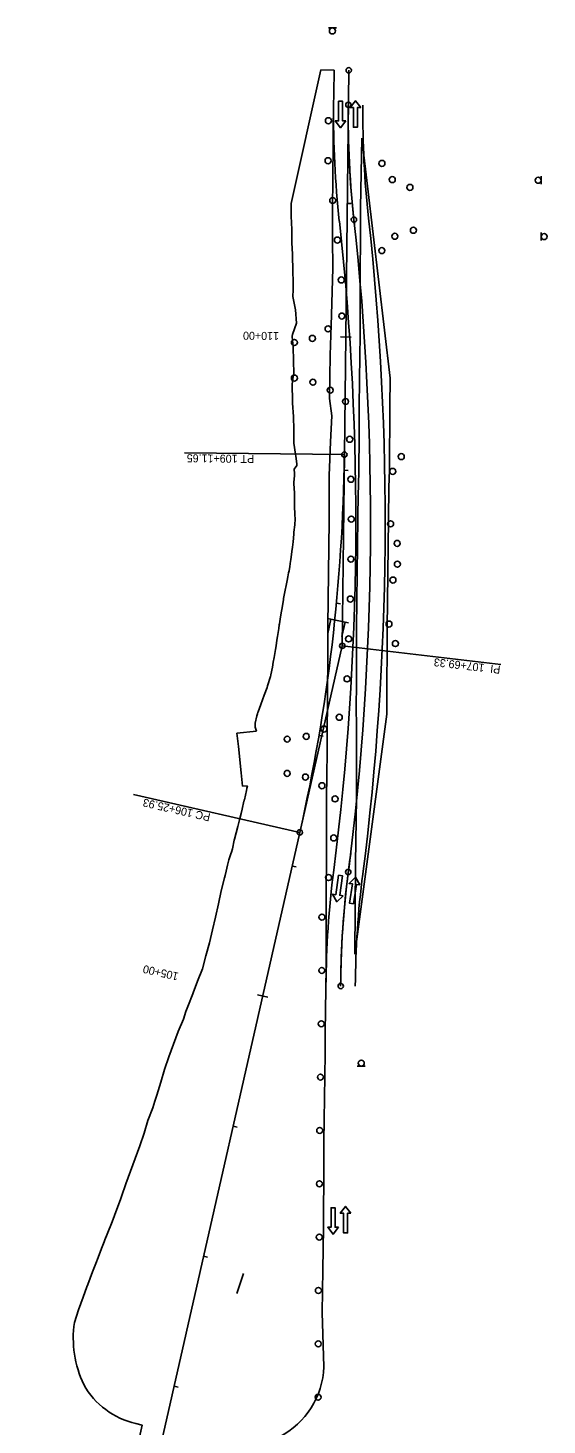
# Model space of a CAD drawing. Extents: x 1710760 to 1712674, y 548603 to 551129.
# Drawn here: x 1712247 to 1712636, y 550081 to 551129 of the extents above; entities that cross this region are included whole.
import ezdxf

# ---------------------------------------------------------------- set-up
doc = ezdxf.new("R2010")
doc.units = 0
for name, color, linetype in [('R_Concrete', 7, 'Continuous'), ('R_Horz Alg', 7, 'Continuous'), ('R_Horz Alg Annot', 7, 'Continuous'), ('R_MOT', 7, 'Continuous'), ('R_Striping', 7, 'Continuous')]:
    doc.layers.add(name, color=color, linetype=linetype)

msp = doc.modelspace()

# ---------------------------------------------------------------- linework, layer by layer
at = {"layer": 'R_Concrete'}
msp.add_line((1712408.5, 550195), (1712403.5, 550179.9), dxfattribs=at)
at = {"layer": 'R_Horz Alg'}
for p, q in [((1712484.2, 550809.1), (1712487.5, 551097.3)), ((1712484.2, 550809.1), (1712487.5, 551097.3)), ((1712246.8, 549627.3), (1712450.8, 550525.8)), ((1712246.8, 549627.3), (1712450.8, 550525.8))]:
    msp.add_line(p, q, dxfattribs=at)
for centre, radius, start, end in [((1713203.3, 551063.2), 716.2, 179.3424, 186.2485), ((1710420.3, 550758.5), 2083.5, 352.7611, 6.2485), ((1711136.1, 550824.3), 1348.1, 347.2066, 359.3498), ((1711136.1, 550824.3), 1348.1, 347.2066, 359.3498), ((1713197.6, 550405.7), 716.2, 172.7611, 179.6146)]:
    msp.add_arc(centre, radius, start, end, dxfattribs=at)
at = {"layer": 'R_Horz Alg Annot'}
for p, q in [((1712482.6, 550665.7), (1712484.2, 550809.1)), ((1712482.6, 550665.7), (1712484.2, 550809.1)), ((1712450.8, 550525.8), (1712482.6, 550665.7)), ((1712450.8, 550525.8), (1712482.6, 550665.7))]:
    msp.add_line(p, q, dxfattribs=at)
for points in [[(1712489.3, 550997.4), (1712486.3, 550997.4)], [(1712481.2, 550897.4), (1712489.2, 550897.3)], [(1712484.2, 550809.1), (1712364.2, 550810.4)], [(1712487, 550797.3), (1712484, 550797.4)], [(1712481.3, 550697.3), (1712478.3, 550697.6)], [(1712482.6, 550665.7), (1712601.7, 550651.6)], [(1712468.2, 550598), (1712465.2, 550598.5)], [(1712450.8, 550525.8), (1712326.1, 550554.2)], [(1712448, 550499.9), (1712445.1, 550500.5)], [(1712419, 550403.9), (1712426.8, 550402.1)], [(1712403.7, 550304.8), (1712400.8, 550305.5)], [(1712381.6, 550207.3), (1712378.6, 550208)], [(1712359.4, 550109.8), (1712356.5, 550110.5)]]:
    msp.add_lwpolyline(points, dxfattribs=at)
for centre in [(1712487.5, 551097.3), (1712487.5, 551097.3), (1712487.2, 551071.4), (1712491.4, 550985.3), (1712484.2, 550809.1), (1712484.2, 550809.1), (1712482.6, 550665.7), (1712482.6, 550665.7), (1712450.8, 550525.8), (1712450.8, 550525.8), (1712487.1, 550496), (1712481.5, 550410.5)]:
    msp.add_circle(centre, 2, dxfattribs=at)
at = {"layer": 'R_MOT'}
for p, q in [((1712472.2, 551129.1), (1712478.2, 551129.1)), ((1712518.6, 550866.5), (1712497.3, 551046.5)), ((1712631.8, 551017.8), (1712631.8, 551011.8)), ((1712631.8, 550969.6), (1712631.8, 550975.6)), ((1712446.3, 550869.8), (1712445.8, 550889.8)), ((1712446.3, 550869.8), (1712445.8, 550889.8)), ((1712487.3, 550682.9), (1712471.6, 550686.2)), ((1712471.8, 550675), (1712474.1, 550685.7)), ((1712482.4, 550672.7), (1712484.7, 550683.4)), ((1712492.1, 550434.5), (1712516.1, 550614.5)), ((1712403.6, 550600.2), (1712418.3, 550601.8)), ((1712403.6, 550600.2), (1712418.3, 550601.8)), ((1712404.7, 550590.3), (1712403.6, 550600.2)), ((1712404.7, 550590.3), (1712403.6, 550600.2)), ((1712406.8, 550570.4), (1712404.7, 550590.3)), ((1712406.8, 550570.4), (1712404.7, 550590.3)), ((1712407.9, 550560.4), (1712406.8, 550570.4)), ((1712407.9, 550560.4), (1712406.8, 550570.4)), ((1712411.5, 550560.8), (1712407.9, 550560.4)), ((1712411.5, 550560.8), (1712407.9, 550560.4)), ((1712499.9, 550350.4), (1712493.9, 550350.4)), ((1712311, 549985), (1712332.5, 550081.3)), ((1712311, 549985), (1712332.5, 550081.3)), ((1712332.5, 550081.3), (1712327.7, 550082.4)), ((1712332.5, 550081.3), (1712327.7, 550082.4))]:
    msp.add_line(p, q, dxfattribs=at)
for points in [[(1712444.2, 550997.5), (1712466.6, 551097.6), (1712476.6, 551097.5)], [(1712444.2, 550997.5), (1712466.6, 551097.6), (1712476.6, 551097.5)], [(1712476.6, 551097.5), (1712476.5, 551095.4), (1712476.3, 551081.9), (1712476.1, 551068.3), (1712475.9, 551054.8), (1712475.7, 551041.2), (1712475.5, 551017), (1712475.4, 550992.8), (1712475.4, 550970.9), (1712475.5, 550949), (1712475.1, 550931.4), (1712474.6, 550913.9), (1712474.1, 550898.7), (1712473.5, 550883.6), (1712473.2, 550867.3), (1712473, 550851.1), (1712474.7, 550838.2), (1712473.9, 550818.8), (1712473.1, 550799.5), (1712472.9, 550793.7), (1712472.8, 550791.4), (1712472.8, 550775.5), (1712472.7, 550759.7), (1712472.5, 550739.9), (1712472.3, 550720.2), (1712472.1, 550700.5), (1712471.9, 550680.8), (1712471.8, 550665.9), (1712471.7, 550651), (1712471.6, 550636.1), (1712471.5, 550621.2), (1712471.4, 550603.7), (1712471.2, 550586.2), (1712471.1, 550568.6), (1712470.9, 550551.1), (1712470.9, 550534.8), (1712470.8, 550518.4), (1712470.7, 550502.1), (1712470.6, 550485.8), (1712470.6, 550470.5), (1712470.6, 550455.2), (1712470.5, 550439.9), (1712470.5, 550424.6), (1712470.3, 550408.4), (1712470.1, 550392.2), (1712469.9, 550376), (1712469.7, 550359.8), (1712469.5, 550343.3), (1712469.2, 550326.8), (1712469, 550310.3), (1712468.7, 550293.8), (1712468.7, 550277.7), (1712468.7, 550261.6), (1712468.6, 550245.4), (1712468.6, 550229.3), (1712468.4, 550213.4), (1712468.1, 550197.6), (1712467.9, 550181.7), (1712467.6, 550165.8), (1712468.8, 550124.9), (1712468.8, 550124.9)], [(1712476.6, 551097.5), (1712476.5, 551095.4), (1712476.3, 551081.9), (1712476.1, 551068.3), (1712475.9, 551054.8), (1712475.7, 551041.2), (1712475.5, 551017), (1712475.4, 550992.8), (1712475.4, 550970.9), (1712475.5, 550949), (1712475.1, 550931.4), (1712474.6, 550913.9), (1712474.1, 550898.7), (1712473.5, 550883.6), (1712473.2, 550867.3), (1712473, 550851.1), (1712474.7, 550838.2), (1712473.9, 550818.8), (1712473.1, 550799.5), (1712472.9, 550793.7), (1712472.8, 550791.4), (1712472.8, 550775.5), (1712472.7, 550759.7), (1712472.5, 550739.9), (1712472.3, 550720.2), (1712472.1, 550700.5), (1712471.9, 550680.8), (1712471.8, 550665.9), (1712471.7, 550651), (1712471.6, 550636.1), (1712471.5, 550621.2), (1712471.4, 550603.7), (1712471.2, 550586.2), (1712471.1, 550568.6), (1712470.9, 550551.1), (1712470.9, 550534.8), (1712470.8, 550518.4), (1712470.7, 550502.1), (1712470.6, 550485.8), (1712470.6, 550470.5), (1712470.6, 550455.2), (1712470.5, 550439.9), (1712470.5, 550424.6), (1712470.3, 550408.4), (1712470.1, 550392.2), (1712469.9, 550376), (1712469.7, 550359.8), (1712469.5, 550343.3), (1712469.2, 550326.8), (1712469, 550310.3), (1712468.7, 550293.8), (1712468.7, 550277.7), (1712468.7, 550261.6), (1712468.6, 550245.4), (1712468.6, 550229.3), (1712468.4, 550213.4), (1712468.1, 550197.6), (1712467.9, 550181.7), (1712467.6, 550165.8), (1712468.8, 550124.9), (1712468.8, 550124.9)], [(1712497.3, 551046.5), (1712496.4, 550994.1), (1712496.3, 550970.5), (1712496.1, 550946.9), (1712496.1, 550929.6), (1712496, 550912.4), (1712496, 550897.9), (1712495.9, 550883.5), (1712495.6, 550864.5), (1712495.3, 550845.5), (1712495.2, 550821.9), (1712495.1, 550798.3), (1712494.7, 550785.1), (1712494.6, 550779.9), (1712494.3, 550761.1), (1712494, 550740.6), (1712493.8, 550720.1), (1712493.6, 550699.6), (1712493.4, 550679), (1712493.3, 550664.5), (1712493.2, 550650), (1712493.2, 550635.6), (1712493.1, 550621.1), (1712493.2, 550603.6), (1712493.2, 550586.2), (1712493.3, 550568.8), (1712493.4, 550551.4), (1712493.1, 550535.2), (1712492.8, 550519), (1712492.6, 550502.7), (1712492.1, 550434.5)], [(1712445.8, 550889.8), (1712445, 550897.8), (1712445, 550897.9), (1712445.2, 550899.2), (1712448.4, 550907.8), (1712447.6, 550917.8), (1712445.6, 550927.8), (1712445.7, 550932.8), (1712445.7, 550937.8), (1712445.6, 550947.8), (1712445.2, 550957.9), (1712445.2, 550959.5), (1712444.9, 550967.9), (1712444.8, 550977.9), (1712444.4, 550987.9), (1712444.2, 550997.5)], [(1712445.8, 550889.8), (1712445, 550897.8), (1712445, 550897.9), (1712445.2, 550899.2), (1712448.4, 550907.8), (1712447.6, 550917.8), (1712445.6, 550927.8), (1712445.7, 550932.8), (1712445.7, 550937.8), (1712445.6, 550947.8), (1712445.2, 550957.9), (1712445.2, 550959.5), (1712444.9, 550967.9), (1712444.8, 550977.9), (1712444.4, 550987.9), (1712444.2, 550997.5)], [(1712444.8, 550736.4), (1712445.2, 550739.8), (1712445.7, 550743.7), (1712446.3, 550749.5), (1712446.4, 550750.9), (1712447, 550756.4), (1712447.1, 550758.2), (1712447.2, 550759.2), (1712447.2, 550760.8), (1712447.1, 550764.2), (1712447, 550765.6), (1712446.9, 550768.9), (1712446.8, 550772.9), (1712446.8, 550778.7), (1712446.7, 550780.2), (1712446.4, 550787.5), (1712446.4, 550788.4), (1712446.7, 550793.1), (1712446.7, 550794.9), (1712446.5, 550798.2), (1712448.6, 550800.9), (1712448.5, 550802.1), (1712447.7, 550807.9), (1712447.5, 550809.5), (1712446.4, 550817.8), (1712446.2, 550826.2), (1712446.2, 550827.8), (1712446, 550837.8), (1712445.3, 550847.8), (1712445.2, 550853.5), (1712445, 550857.8), (1712445, 550861.9), (1712445.9, 550867.8), (1712446.3, 550869.8)], [(1712444.8, 550736.4), (1712445.2, 550739.8), (1712445.7, 550743.7), (1712446.3, 550749.5), (1712446.4, 550750.9), (1712447, 550756.4), (1712447.1, 550758.2), (1712447.2, 550759.2), (1712447.2, 550760.8), (1712447.1, 550764.2), (1712447, 550765.6), (1712446.9, 550768.9), (1712446.8, 550772.9), (1712446.8, 550778.7), (1712446.7, 550780.2), (1712446.4, 550787.5), (1712446.4, 550788.4), (1712446.7, 550793.1), (1712446.7, 550794.9), (1712446.5, 550798.2), (1712448.6, 550800.9), (1712448.5, 550802.1), (1712447.7, 550807.9), (1712447.5, 550809.5), (1712446.4, 550817.8), (1712446.2, 550826.2), (1712446.2, 550827.8), (1712446, 550837.8), (1712445.3, 550847.8), (1712445.2, 550853.5), (1712445, 550857.8), (1712445, 550861.9), (1712445.9, 550867.8), (1712446.3, 550869.8)], [(1712516.1, 550614.5), (1712516.1, 550621), (1712516.4, 550678.9), (1712517.3, 550760.8), (1712517.7, 550784.5), (1712518.1, 550797.8), (1712518.3, 550845.3), (1712518.6, 550866.5)], [(1712418.3, 550601.8), (1712417.4, 550604.8), (1712417.3, 550606.6), (1712417.3, 550607.1), (1712417.3, 550607.6), (1712417.3, 550607.7), (1712418.5, 550613.3), (1712419, 550614.8), (1712419.3, 550616), (1712419.5, 550616.3), (1712421.5, 550621.7), (1712422.8, 550625.3), (1712424.1, 550628.7), (1712426.2, 550634.5), (1712426.6, 550635.6), (1712428.7, 550642.7), (1712429, 550643.8), (1712429, 550643.9), (1712430.2, 550649.8), (1712430.9, 550653.4), (1712431.6, 550657), (1712432.5, 550663), (1712432.7, 550664.2), (1712433.9, 550671.4), (1712434.1, 550672.6), (1712435, 550678.6), (1712435.4, 550681.4), (1712435.6, 550682.1), (1712436.1, 550685.8), (1712436.6, 550689), (1712437, 550691.7), (1712437.2, 550693), (1712438.5, 550700.2), (1712438.6, 550701.3), (1712439.8, 550707.4), (1712440.5, 550710.9), (1712441.2, 550714.7), (1712441.7, 550717.5), (1712442.4, 550720.5), (1712442.7, 550721.9), (1712443.2, 550725.2), (1712443.9, 550729.1), (1712444, 550730.1), (1712444.8, 550736.4)], [(1712418.3, 550601.8), (1712417.4, 550604.8), (1712417.3, 550606.6), (1712417.3, 550607.1), (1712417.3, 550607.6), (1712417.3, 550607.7), (1712418.5, 550613.3), (1712419, 550614.8), (1712419.3, 550616), (1712419.5, 550616.3), (1712421.5, 550621.7), (1712422.8, 550625.3), (1712424.1, 550628.7), (1712426.2, 550634.5), (1712426.6, 550635.6), (1712428.7, 550642.7), (1712429, 550643.8), (1712429, 550643.9), (1712430.2, 550649.8), (1712430.9, 550653.4), (1712431.6, 550657), (1712432.5, 550663), (1712432.7, 550664.2), (1712433.9, 550671.4), (1712434.1, 550672.6), (1712435, 550678.6), (1712435.4, 550681.4), (1712435.6, 550682.1), (1712436.1, 550685.8), (1712436.6, 550689), (1712437, 550691.7), (1712437.2, 550693), (1712438.5, 550700.2), (1712438.6, 550701.3), (1712439.8, 550707.4), (1712440.5, 550710.9), (1712441.2, 550714.7), (1712441.7, 550717.5), (1712442.4, 550720.5), (1712442.7, 550721.9), (1712443.2, 550725.2), (1712443.9, 550729.1), (1712444, 550730.1), (1712444.8, 550736.4)], [(1712281.6, 550158.2), (1712284.7, 550167.8), (1712288.1, 550177.3), (1712291, 550184.9), (1712291.6, 550186.7), (1712295.3, 550196.2), (1712298.2, 550203.8), (1712298.9, 550205.6), (1712302.6, 550215), (1712304, 550218.7), (1712304.6, 550220.3), (1712306.2, 550224.4), (1712309.9, 550233.8), (1712313.5, 550243.3), (1712316.2, 550250.4), (1712317, 550252.8), (1712320.2, 550262.3), (1712323.7, 550271.7), (1712327.3, 550281.2), (1712330.7, 550290.7), (1712333.9, 550300.2), (1712336.8, 550309.8), (1712340.4, 550319.2), (1712341.9, 550324.1), (1712343.4, 550328.8), (1712346.4, 550338.4), (1712349.3, 550348), (1712352.5, 550357.5), (1712356.1, 550366.9), (1712359.6, 550376.4), (1712363.4, 550385.8), (1712365.3, 550391.4), (1712366.8, 550395.3), (1712370.5, 550404.7), (1712370.8, 550405.5), (1712374.1, 550414.1), (1712377.8, 550423.5), (1712380.3, 550433.2), (1712382.9, 550442.9), (1712385.3, 550452.6), (1712387.5, 550462.3), (1712389.8, 550472.1), (1712391.8, 550481.9), (1712394.3, 550491.6), (1712394.8, 550493.5), (1712395.6, 550496.8), (1712396.6, 550501.3), (1712397.6, 550505.2), (1712397.6, 550505.2), (1712397.6, 550505.2), (1712399, 550509.8), (1712399.4, 550510.9), (1712400.2, 550513.4), (1712401.5, 550519.9), (1712401.7, 550520.6), (1712404.3, 550530.3), (1712405.7, 550536.1), (1712406.7, 550539.9), (1712407.5, 550543.1), (1712408.9, 550549.2), (1712408.9, 550549.3), (1712409, 550549.5), (1712409.1, 550550.2), (1712409.2, 550550.2), (1712410.7, 550557.3), (1712411, 550558.7), (1712411.1, 550558.9), (1712411.5, 550560.8)], [(1712281.6, 550158.2), (1712284.7, 550167.8), (1712288.1, 550177.3), (1712291, 550184.9), (1712291.6, 550186.7), (1712295.3, 550196.2), (1712298.2, 550203.8), (1712298.9, 550205.6), (1712302.6, 550215), (1712304, 550218.7), (1712304.6, 550220.3), (1712306.2, 550224.4), (1712309.9, 550233.8), (1712313.5, 550243.3), (1712316.2, 550250.4), (1712317, 550252.8), (1712320.2, 550262.3), (1712323.7, 550271.7), (1712327.3, 550281.2), (1712330.7, 550290.7), (1712333.9, 550300.2), (1712336.8, 550309.8), (1712340.4, 550319.2), (1712341.9, 550324.1), (1712343.4, 550328.8), (1712346.4, 550338.4), (1712349.3, 550348), (1712352.5, 550357.5), (1712356.1, 550366.9), (1712359.6, 550376.4), (1712363.4, 550385.8), (1712365.3, 550391.4), (1712366.8, 550395.3), (1712370.5, 550404.7), (1712370.8, 550405.5), (1712374.1, 550414.1), (1712377.8, 550423.5), (1712380.3, 550433.2), (1712382.9, 550442.9), (1712385.3, 550452.6), (1712387.5, 550462.3), (1712389.8, 550472.1), (1712391.8, 550481.9), (1712394.3, 550491.6), (1712394.8, 550493.5), (1712395.6, 550496.8), (1712396.6, 550501.3), (1712397.6, 550505.2), (1712397.6, 550505.2), (1712397.6, 550505.2), (1712399, 550509.8), (1712399.4, 550510.9), (1712400.2, 550513.4), (1712401.5, 550519.9), (1712401.7, 550520.6), (1712404.3, 550530.3), (1712405.7, 550536.1), (1712406.7, 550539.9), (1712407.5, 550543.1), (1712408.9, 550549.2), (1712408.9, 550549.3), (1712409, 550549.5), (1712409.1, 550550.2), (1712409.2, 550550.2), (1712410.7, 550557.3), (1712411, 550558.7), (1712411.1, 550558.9), (1712411.5, 550560.8)]]:
    msp.add_lwpolyline(points, dxfattribs=at)
for points in [[(1712485.4, 551059.4), (1712481.4, 551054.2), (1712477.4, 551059.4), (1712479.9, 551059.4), (1712479.9, 551074.1), (1712482.9, 551074.1), (1712482.9, 551059.4)], [(1712496.5, 551069.3), (1712492.5, 551074.5), (1712488.5, 551069.3), (1712491, 551069.3), (1712491, 551054.6), (1712494, 551054.6), (1712494, 551069.3)], [(1712483.2, 550478.2), (1712478.5, 550473.7), (1712475.3, 550479.4), (1712477.7, 550479), (1712479.9, 550493.6), (1712482.9, 550493.1), (1712480.7, 550478.6)], [(1712495.7, 550486.4), (1712492.5, 550492.1), (1712487.7, 550487.5), (1712490.2, 550487.2), (1712488.1, 550472.6), (1712491, 550472.2), (1712493.2, 550486.7)], [(1712479.7, 550229.6), (1712475.7, 550224.4), (1712471.7, 550229.6), (1712474.2, 550229.6), (1712474.2, 550244.3), (1712477.2, 550244.3), (1712477.2, 550229.6)], [(1712489.1, 550240.1), (1712485.1, 550245.3), (1712481.1, 550240.1), (1712483.6, 550240.1), (1712483.6, 550225.4), (1712486.6, 550225.4), (1712486.6, 550240.1)]]:
    msp.add_lwpolyline(points, close=True, dxfattribs=at)
for centre in [(1712475.2, 551126.8), (1712472.2, 551059.5), (1712472, 551029.5), (1712512.4, 551027.5), (1712520.2, 551015.3), (1712533.4, 551009.5), (1712629.6, 551014.8), (1712475.5, 550999.7), (1712536, 550977.3), (1712479, 550970), (1712522.1, 550972.8), (1712634.1, 550972.6), (1712512.3, 550962.1), (1712481.9, 550940.1), (1712482.3, 550913), (1712472, 550903.4), (1712446.7, 550893.2), (1712460.2, 550896.3), (1712446.7, 550866.5), (1712460.6, 550863.4), (1712473.6, 550857.4), (1712485.1, 550848.9), (1712488.2, 550820.6), (1712526.9, 550807.6), (1712489.1, 550790.6), (1712520.5, 550796.5), (1712489.4, 550760.7), (1712518.9, 550757.2), (1712523.8, 550742.5), (1712489.1, 550730.7), (1712524, 550726.9), (1712520.7, 550715), (1712488.7, 550700.8), (1712517.7, 550682), (1712487.4, 550670.9), (1712522.5, 550667.4), (1712486.2, 550640.9), (1712480.4, 550612.1), (1712455.6, 550597.8), (1712468.9, 550603.3), (1712441.3, 550595.7), (1712441.3, 550570), (1712455, 550567.3), (1712467.4, 550560.8), (1712477.2, 550550.9), (1712476.2, 550521.6), (1712472.4, 550491.9), (1712467.4, 550462.2), (1712467.3, 550422.2), (1712466.9, 550382.2), (1712496.9, 550352.7), (1712466.3, 550342.2), (1712465.7, 550302.2), (1712465.5, 550262.2), (1712465.4, 550222.2), (1712464.7, 550182.2), (1712464.6, 550142.2), (1712464.5, 550102.2)]:
    msp.add_circle(centre, 2.25, dxfattribs=at)
for centre, radius, start, end in [((1713203.3, 551063.3), 716.2, 179.3498, 186.5309), ((1713197.6, 550405.7), 716.2, 171.6407, 179.6146), ((1712363.1, 550146.8), 82.3, 171.9815, 205.2972), ((1712363.1, 550146.8), 82.3, 171.9815, 205.2972), ((1712407.7, 550126.9), 61.1, 297.0662, 358.1873), ((1712407.7, 550126.9), 61.1, 297.0662, 358.1873), ((1712341, 550140.8), 59.9, 209.1714, 257.2066), ((1712341, 550140.8), 59.9, 209.1714, 257.2066)]:
    msp.add_arc(centre, radius, start, end, dxfattribs=at)
at = {"layer": 'R_Striping'}
for centre, radius, start, end in [((1713203.3, 551063.2), 727.2, 179.3424, 186.2485), ((1713203.3, 551063.2), 716.2, 179.3424, 186.2485), ((1713203.3, 551063.2), 705.2, 179.3424, 186.2485), ((1710420.3, 550758.5), 2072.5, 352.7611, 6.2485), ((1710420.3, 550758.5), 2083.5, 352.7611, 6.2485), ((1710420.3, 550758.5), 2094.5, 352.7611, 6.2485), ((1713197.6, 550405.7), 727.2, 172.7611, 179.6146), ((1713197.6, 550405.7), 716.2, 172.7611, 179.6146), ((1713197.6, 550405.7), 705.2, 172.7611, 179.6146)]:
    msp.add_arc(centre, radius, start, end, dxfattribs=at)

# ---------------------------------------------------------------- texts
at = {"layer": 'R_Horz Alg Annot'}
for s, rotation, p in [('110+00', 179.3498, (1712435.2, 550901)), ('PT 109+11.65', 179.3498, (1712416.6, 550808.8)), ('PI  107+69.33', 173.2782, (1712601.6, 550650.6)), ('PC 106+25.93', 167.2066, (1712384.1, 550539.8)), ('105+00', 167.2066, (1712360.2, 550420.4))]:
    msp.add_text(s, height=6, rotation=rotation, dxfattribs=at).set_placement(p)

doc.saveas('drawing.dxf')
